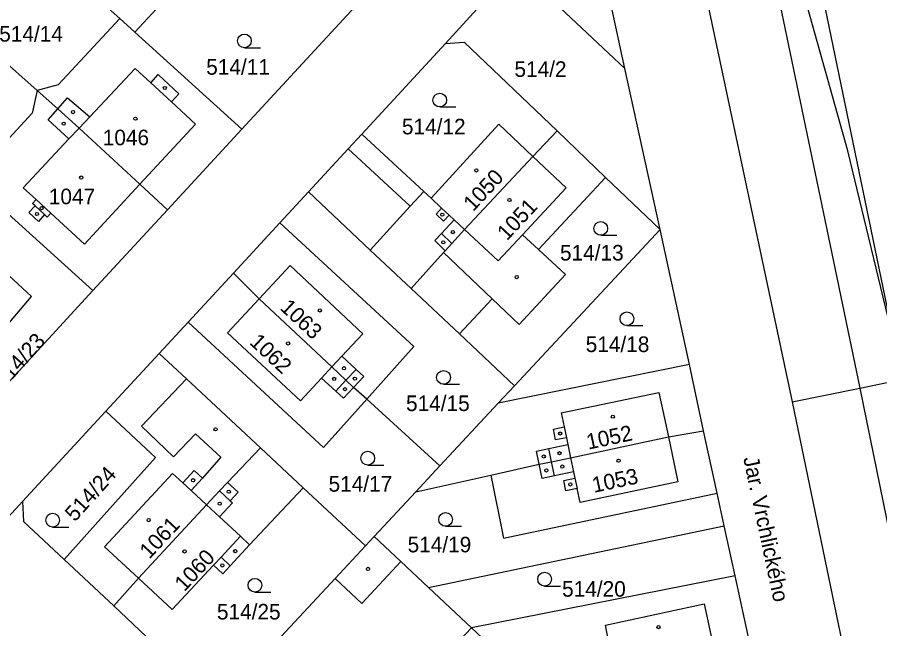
# Model space of a CAD drawing. Extents: x -679220 to -673243, y -1075091 to -1066557.
# Drawn here: x -675837.1 to -675742.9, y -1071866.6 to -1071799.9 of the extents above; entities that cross this region are included whole.
import ezdxf

# ---------------------------------------------------------------- set-up
doc = ezdxf.new("R2010")
doc.units = 0
for name, color, linetype in [('Hranice parcel', 7, 'Continuous'), ('Parcelní čísla', 7, 'Continuous'), ('Pop  PČ popisy', 7, 'Continuous'), ('Poz předměty', 7, 'Continuous'), ('Vnitřní kresba', 7, 'Continuous'), ('Značky budov', 7, 'Continuous'), ('Značky kultur', 7, 'Continuous')]:
    doc.layers.add(name, color=color, linetype=linetype)

msp = doc.modelspace()

# ---------------------------------------------------------------- linework, layer by layer
at = {"layer": 'Hranice parcel'}
for p, q in [((-675770.76, -1071805.49), (-675775, -1071786.1)), ((-675835.95, -1071790.96), (-675825.92, -1071800.04)), ((-675782.65, -1071794.34), (-675790.35, -1071802.75)), ((-675770.76, -1071805.49), (-675782.65, -1071794.34)), ((-675812.58, -1071812.11), (-675797.69, -1071795.96)), ((-675824.28, -1071801.52), (-675821.44, -1071798.48)), ((-675844.12, -1071799.72), (-675834.93, -1071807.9)), ((-675824.28, -1071801.52), (-675825.92, -1071800.04)), ((-675812.58, -1071812.11), (-675824.28, -1071801.52)), ((-675766.92, -1071823.05), (-675770.76, -1071805.49)), ((-675820.71, -1071820.92), (-675812.58, -1071812.11)), ((-675778.16, -1071812.31), (-675780.82, -1071815.1)), ((-675772.86, -1071817.38), (-675778.16, -1071812.31)), ((-675772.86, -1071817.38), (-675766.92, -1071823.05)), ((-675840.56, -1071819.13), (-675828.84, -1071829.74)), ((-675805.32, -1071818.96), (-675808.44, -1071822.34)), ((-675805.32, -1071818.96), (-675798.56, -1071825.31)), ((-675828.84, -1071829.74), (-675820.71, -1071820.92)), ((-675808.44, -1071822.34), (-675813.5, -1071827.82)), ((-675782.82, -1071840.12), (-675766.92, -1071823.05)), ((-675763.72, -1071837.81), (-675766.92, -1071823.05)), ((-675798.56, -1071825.31), (-675794.1, -1071829.51)), ((-675813.5, -1071827.82), (-675818.46, -1071833.19)), ((-675794.1, -1071829.51), (-675788.83, -1071834.47)), ((-675818.46, -1071833.19), (-675821.6, -1071836.59)), ((-675788.83, -1071834.47), (-675782.82, -1071840.12)), ((-675821.6, -1071836.59), (-675827.44, -1071842.91)), ((-675763.72, -1071837.81), (-675784.58, -1071842.01)), ((-675762.16, -1071845.04), (-675763.72, -1071837.81)), ((-675784.58, -1071842.01), (-675782.82, -1071840.12)), ((-675798.92, -1071841.57), (-675790.95, -1071848.86)), ((-675784.58, -1071842.01), (-675790.95, -1071848.86)), ((-675827.44, -1071842.91), (-675836.53, -1071852.75)), ((-675760.69, -1071851.83), (-675762.16, -1071845.04)), ((-675805.89, -1071851.26), (-675810.55, -1071846.9)), ((-675790.95, -1071848.86), (-675793.57, -1071851.68)), ((-675793.57, -1071851.68), (-675785.4, -1071849.86)), ((-675805.89, -1071851.26), (-675799.09, -1071857.6)), ((-675798.13, -1071856.58), (-675793.57, -1071851.68)), ((-675759.92, -1071855.39), (-675760.69, -1071851.83)), ((-675845.47, -1071862.48), (-675836.53, -1071852.75)), ((-675792.2, -1071862.14), (-675759.92, -1071855.39)), ((-675758.73, -1071860.87), (-675759.92, -1071855.39)), ((-675798.13, -1071856.58), (-675799.09, -1071857.6)), ((-675831.97, -1071859.1), (-675826.57, -1071864.15)), ((-675758.73, -1071860.87), (-675787.52, -1071866.53)), ((-675757.17, -1071868.06), (-675758.73, -1071860.87)), ((-675826.57, -1071864.15), (-675823.88, -1071861.12)), ((-675787.52, -1071866.53), (-675792.2, -1071862.14)), ((-675826.57, -1071864.15), (-675815.16, -1071874.86)), ((-675787.52, -1071866.53), (-675784.09, -1071869.74))]:
    msp.add_line(p, q, dxfattribs=at)
for points in [[(-675791.003, -1071658.205), (-675790.75, -1071659.46), (-675779.94, -1071713.34), (-675771.38, -1071755.76), (-675762.14, -1071796.42), (-675752.49, -1071841.88)], [(-675825.92, -1071800.04), (-675832.64, -1071807.29), (-675834.93, -1071807.9)], [(-675790.35, -1071802.75), (-675788.32, -1071802.61), (-675778.16, -1071812.31)], [(-675790.35, -1071802.75), (-675799.5, -1071812.66), (-675800.98, -1071814.26), (-675805.32, -1071818.96)], [(-675834.93, -1071807.9), (-675835.49, -1071810.37), (-675842.22, -1071817.63)], [(-675834.93, -1071807.9), (-675832.69, -1071809.89), (-675830.34, -1071811.99), (-675823.71, -1071818.12), (-675820.71, -1071820.92)], [(-675780.82, -1071815.1), (-675784.51, -1071811.58), (-675791.92, -1071819.66), (-675792.73, -1071818.92), (-675794.2, -1071820.51), (-675798.56, -1071825.31)], [(-675794.1, -1071829.51), (-675790.55, -1071825.58), (-675790.38, -1071825.4), (-675789.67, -1071824.61), (-675788.27, -1071823.06), (-675780.82, -1071815.1)], [(-675788.83, -1071834.47), (-675785.25, -1071830.63), (-675782.32, -1071833.43), (-675777.26, -1071827.98), (-675780.2, -1071825.24), (-675772.86, -1071817.38)], [(-675798.92, -1071841.57), (-675793.79, -1071835.84), (-675808.44, -1071822.34)], [(-675848.43, -1071843.7), (-675843.75, -1071838.95), (-675842.57, -1071838.65), (-675835.54, -1071830.36), (-675843.93, -1071822.65)], [(-675798.92, -1071841.57), (-675800.39, -1071840.3), (-675801.23, -1071839.51), (-675802.75, -1071838.07), (-675810.7, -1071830.63), (-675813.5, -1071827.82)], [(-675845.89, -1071846.03), (-675843.82, -1071845.98), (-675828.84, -1071829.74)], [(-675818.46, -1071833.19), (-675803.66, -1071846.86), (-675798.92, -1071841.57)], [(-675810.55, -1071846.9), (-675818.63, -1071839.36), (-675821.6, -1071836.59)], [(-675752.49, -1071841.88), (-675745.12, -1071840.38), (-675740.55, -1071839.44), (-675734.17, -1071838.14)], [(-675752.49, -1071841.88), (-675742.66, -1071889.28), (-675729.17, -1071951.83), (-675725.47, -1071968.71), (-675720.4, -1071992.09), (-675718.71, -1072000.24), (-675717.07, -1072008.06), (-675709.67, -1072042.49)], [(-675827.44, -1071842.91), (-675822.03, -1071847.94), (-675831.97, -1071859.1)], [(-675785.4, -1071849.86), (-675780.11, -1071848.69), (-675778.77, -1071848.41), (-675776.69, -1071847.97), (-675766.01, -1071845.71), (-675762.16, -1071845.04)], [(-675810.55, -1071846.9), (-675814.17, -1071850.66), (-675815.02, -1071851.58), (-675816.45, -1071853.12), (-675823.88, -1071861.12)], [(-675785.4, -1071849.86), (-675784.01, -1071856.75), (-675760.69, -1071851.83)], [(-675823.88, -1071861.12), (-675820.18, -1071864.55), (-675815.68, -1071859.71), (-675814.67, -1071860.64), (-675813.85, -1071859.76), (-675811.76, -1071857.47), (-675805.89, -1071851.26)], [(-675836.53, -1071852.75), (-675836.43, -1071854.92), (-675831.97, -1071859.1)], [(-675792.2, -1071862.14), (-675795.22, -1071859.31), (-675798.13, -1071856.58)], [(-675799.09, -1071857.6), (-675802.4, -1071861.16), (-675815.16, -1071874.86)], [(-675787.52, -1071866.53), (-675792.07, -1071871.33), (-675792.89, -1071872.21), (-675794.33, -1071873.74), (-675801.82, -1071881.71), (-675804.58, -1071884.78)]]:
    msp.add_lwpolyline(points, dxfattribs=at)
at = {"layer": 'Poz předměty'}
for p, q in [((-675750.23, -1071792.42), (-675741.3, -1071835.73)), ((-675754.78, -1071793.86), (-675748.18, -1071825.68)), ((-675746.4, -1071814.48), (-675752.28, -1071793.55)), ((-675741.3, -1071835.73), (-675746.4, -1071814.48)), ((-675748.18, -1071825.68), (-675745.12, -1071840.38)), ((-675745.12, -1071840.38), (-675738.42, -1071873.24))]:
    msp.add_line(p, q, dxfattribs=at)
at = {"layer": 'Vnitřní kresba'}
for p, q in [((-675829.19, -1071810.77), (-675824.22, -1071805.48)), ((-675824.22, -1071805.48), (-675822.53, -1071807.04)), ((-675822.53, -1071807.04), (-675821.72, -1071806.16)), ((-675821.72, -1071806.16), (-675819.47, -1071808.24)), ((-675820.28, -1071809.12), (-675822.53, -1071807.04)), ((-675819.47, -1071808.24), (-675820.28, -1071809.12)), ((-675832.69, -1071809.89), (-675831.63, -1071808.7)), ((-675831.63, -1071808.7), (-675829.19, -1071810.77)), ((-675820.28, -1071809.12), (-675817.64, -1071811.56)), ((-675833.75, -1071811.09), (-675832.69, -1071809.89)), ((-675831.46, -1071813.18), (-675833.75, -1071811.09)), ((-675830.34, -1071811.99), (-675829.19, -1071810.77)), ((-675831.46, -1071813.18), (-675830.34, -1071811.99)), ((-675823.71, -1071818.12), (-675817.64, -1071811.56)), ((-675799.5, -1071812.66), (-675792.73, -1071818.92)), ((-675836.46, -1071818.5), (-675831.46, -1071813.18)), ((-675800.98, -1071814.26), (-675794.2, -1071820.51)), ((-675780.82, -1071815.1), (-675777.18, -1071818.52)), ((-675835.05, -1071819.79), (-675836.46, -1071818.5)), ((-675829.77, -1071824.68), (-675823.71, -1071818.12)), ((-675781.94, -1071823.63), (-675777.18, -1071818.52)), ((-675835.83, -1071821.22), (-675835.15, -1071820.49)), ((-675835.45, -1071820.22), (-675835.05, -1071819.79)), ((-675835.15, -1071820.49), (-675835.45, -1071820.22)), ((-675834.12, -1071821.44), (-675835.15, -1071820.49)), ((-675835.05, -1071819.79), (-675833.44, -1071821.29)), ((-675791.92, -1071819.66), (-675790.77, -1071820.73)), ((-675834.8, -1071822.18), (-675835.83, -1071821.22)), ((-675834.12, -1071821.44), (-675834.8, -1071822.18)), ((-675833.83, -1071821.71), (-675834.12, -1071821.44)), ((-675833.44, -1071821.29), (-675833.83, -1071821.71)), ((-675829.77, -1071824.68), (-675833.44, -1071821.29)), ((-675791.38, -1071821.39), (-675790.77, -1071820.73)), ((-675790.57, -1071822.15), (-675791.38, -1071821.39)), ((-675790.77, -1071820.73), (-675789.96, -1071821.49)), ((-675789.96, -1071821.49), (-675790.57, -1071822.15)), ((-675789.96, -1071821.49), (-675789.41, -1071822)), ((-675789.41, -1071822), (-675790.8, -1071823.49)), ((-675789.41, -1071822), (-675788.27, -1071823.06)), ((-675788.27, -1071823.06), (-675784.59, -1071826.48)), ((-675790.8, -1071823.49), (-675791.51, -1071824.26)), ((-675791.51, -1071824.26), (-675790.38, -1071825.4)), ((-675790.8, -1071823.49), (-675789.67, -1071824.61)), ((-675784.59, -1071826.48), (-675781.94, -1071823.63)), ((-675781.94, -1071823.63), (-675780.2, -1071825.24)), ((-675785.25, -1071830.63), (-675790.55, -1071825.58)), ((-675810.7, -1071830.63), (-675807.31, -1071826.99)), ((-675799.38, -1071834.45), (-675807.31, -1071826.99)), ((-675814.16, -1071834.34), (-675810.7, -1071830.63)), ((-675814.16, -1071834.34), (-675806.19, -1071841.76)), ((-675801.66, -1071836.9), (-675799.38, -1071834.45)), ((-675802.75, -1071838.07), (-675801.66, -1071836.9)), ((-675801.66, -1071836.9), (-675800.12, -1071838.33)), ((-675803.88, -1071839.28), (-675802.75, -1071838.07)), ((-675800.12, -1071838.33), (-675801.23, -1071839.51)), ((-675800.12, -1071838.33), (-675799.28, -1071839.12)), ((-675818.63, -1071839.36), (-675823.56, -1071844.54)), ((-675806.19, -1071841.76), (-675803.88, -1071839.28)), ((-675802.34, -1071840.71), (-675803.88, -1071839.28)), ((-675799.28, -1071839.12), (-675800.39, -1071840.3)), ((-675801.23, -1071839.51), (-675802.34, -1071840.71)), ((-675800.39, -1071840.3), (-675801.5, -1071841.49)), ((-675801.5, -1071841.49), (-675802.34, -1071840.71)), ((-675777.72, -1071843.09), (-675767.04, -1071840.84)), ((-675767.04, -1071840.84), (-675766.01, -1071845.71)), ((-675777.72, -1071843.09), (-675777.4, -1071844.61)), ((-675823.56, -1071844.54), (-675820.05, -1071847.89)), ((-675778.57, -1071844.86), (-675777.4, -1071844.61)), ((-675778.33, -1071846.03), (-675778.57, -1071844.86)), ((-675777.4, -1071844.61), (-675777.15, -1071845.79)), ((-675820.05, -1071847.89), (-675817.64, -1071845.35)), ((-675817.64, -1071845.35), (-675814.89, -1071847.92)), ((-675777.15, -1071845.79), (-675778.33, -1071846.03)), ((-675777.15, -1071845.79), (-675777, -1071846.52)), ((-675766.01, -1071845.71), (-675764.98, -1071850.59)), ((-675779.08, -1071846.96), (-675777, -1071846.52)), ((-675777, -1071846.52), (-675776.69, -1071847.97)), ((-675780.42, -1071847.24), (-675779.08, -1071846.96)), ((-675780.11, -1071848.69), (-675780.42, -1071847.24)), ((-675778.77, -1071848.41), (-675779.08, -1071846.96)), ((-675814.89, -1071847.92), (-675816.88, -1071850.2)), ((-675779.79, -1071850.23), (-675780.11, -1071848.69)), ((-675778.45, -1071849.94), (-675778.77, -1071848.41)), ((-675776.69, -1071847.97), (-675776.37, -1071849.5)), ((-675827.58, -1071857.69), (-675820.15, -1071849.68)), ((-675820.15, -1071849.68), (-675819.04, -1071850.71)), ((-675819.04, -1071850.71), (-675817.78, -1071849.36)), ((-675817.78, -1071849.36), (-675816.88, -1071850.2)), ((-675776.37, -1071849.5), (-675778.45, -1071849.94)), ((-675776.37, -1071849.5), (-675776.22, -1071850.19)), ((-675816.88, -1071850.2), (-675818.13, -1071851.55)), ((-675814.17, -1071850.66), (-675813, -1071851.75)), ((-675778.45, -1071849.94), (-675779.79, -1071850.23)), ((-675777.44, -1071850.45), (-675776.22, -1071850.19)), ((-675777.2, -1071851.59), (-675777.44, -1071850.45)), ((-675776.22, -1071850.19), (-675775.98, -1071851.33)), ((-675764.98, -1071850.59), (-675775.66, -1071852.85)), ((-675819.04, -1071850.71), (-675818.13, -1071851.55)), ((-675818.13, -1071851.55), (-675816.45, -1071853.12)), ((-675813.85, -1071852.67), (-675815.02, -1071851.58)), ((-675775.98, -1071851.33), (-675777.2, -1071851.59)), ((-675775.66, -1071852.85), (-675775.98, -1071851.33)), ((-675813, -1071851.75), (-675813.85, -1071852.67)), ((-675816.45, -1071853.12), (-675815.02, -1071854.44)), ((-675815.02, -1071854.44), (-675813.59, -1071852.9)), ((-675813.85, -1071852.67), (-675813.59, -1071852.9)), ((-675815.02, -1071854.44), (-675812.75, -1071856.55)), ((-675814.85, -1071858.82), (-675812.75, -1071856.55)), ((-675812.75, -1071856.55), (-675811.76, -1071857.47)), ((-675823.88, -1071861.12), (-675827.58, -1071857.69)), ((-675815.68, -1071859.71), (-675814.85, -1071858.82)), ((-675814.85, -1071858.82), (-675813.85, -1071859.76)), ((-675795.22, -1071859.31), (-675799.47, -1071863.88)), ((-675799.47, -1071863.88), (-675802.4, -1071861.16)), ((-675772.89, -1071866.24), (-675762.11, -1071863.91)), ((-675762.11, -1071863.91), (-675761.04, -1071868.86)), ((-675772.57, -1071867.76), (-675772.89, -1071866.24))]:
    msp.add_line(p, q, dxfattribs=at)
at = {"layer": 'Značky budov'}
for centre in [(-675820.997, -1071807.619), (-675831.017, -1071810.249), (-675824.207, -1071810.969), (-675832.037, -1071811.509), (-675786.977, -1071816.619), (-675830.127, -1071817.399), (-675783.367, -1071819.849), (-675834.957, -1071821.379), (-675834.447, -1071820.739), (-675790.697, -1071821.449), (-675789.547, -1071823.349), (-675790.587, -1071824.469), (-675782.577, -1071828.259), (-675804.067, -1071831.899), (-675807.537, -1071835.499), (-675801.427, -1071838.209), (-675802.507, -1071839.369), (-675800.237, -1071839.339), (-675801.317, -1071840.489), (-675772.077, -1071843.499), (-675815.457, -1071844.879), (-675777.827, -1071845.329), (-675779.617, -1071847.839), (-675777.897, -1071847.479), (-675777.597, -1071848.939), (-675771.447, -1071848.299), (-675779.337, -1071849.359), (-675817.907, -1071850.429), (-675814.017, -1071851.679), (-675776.717, -1071850.889), (-675815.007, -1071852.989), (-675822.757, -1071854.779), (-675818.837, -1071858.199), (-675813.307, -1071858.169), (-675814.717, -1071859.729), (-675798.817, -1071860.109), (-675767.087, -1071866.459)]:
    msp.add_circle(centre, 0.175, dxfattribs=at)
at = {"layer": 'Značky kultur'}
for p, q in [((-675812.303, -1071803.23), (-675810.553, -1071803.23)), ((-675790.973, -1071809.69), (-675789.223, -1071809.69)), ((-675773.393, -1071823.69), (-675771.643, -1071823.69)), ((-675770.543, -1071833.55), (-675768.793, -1071833.55)), ((-675790.563, -1071839.95), (-675788.813, -1071839.95)), ((-675798.833, -1071848.77), (-675797.083, -1071848.77)), ((-675833.243, -1071855.54), (-675831.493, -1071855.54)), ((-675790.343, -1071855.45), (-675788.593, -1071855.45)), ((-675779.533, -1071861.98), (-675777.783, -1071861.98)), ((-675811.153, -1071862.64), (-675809.403, -1071862.64))]:
    msp.add_line(p, q, dxfattribs=at)
for centre in [(-675812.303, -1071802.48), (-675790.973, -1071808.94), (-675773.393, -1071822.94), (-675770.543, -1071832.8), (-675790.563, -1071839.2), (-675798.833, -1071848.02), (-675833.243, -1071854.79), (-675790.343, -1071854.7), (-675779.533, -1071861.23), (-675811.153, -1071861.89)]:
    msp.add_circle(centre, 0.75, dxfattribs=at)

# ---------------------------------------------------------------- texts
at = {"layer": 'Parcelní čísla'}
for s, p in [('514/14', (-675839.077, -1071802.56)), ('514/11', (-675816.477, -1071806.17)), ('514/2', (-675782.818, -1071806.41)), ('514/12', (-675795.107, -1071812.68)), ('1046', (-675827.774, -1071813.87)), ('1047', (-675833.664, -1071820.31)), ('514/13', (-675777.847, -1071826.45)), ('514/18', (-675775.037, -1071836.44)), ('514/15', (-675794.657, -1071842.88)), ('514/17', (-675803.117, -1071851.68)), ('514/19', (-675794.487, -1071858.3)), ('514/20', (-675777.617, -1071863.14)), ('514/25', (-675815.307, -1071865.63))]:
    msp.add_text(s, height=1.7, dxfattribs=at).set_placement(p)
for s, rotation, p in [('1050', 47, (-675787.326, -1071821.174)), ('1051', 47, (-675783.636, -1071824.364)), ('1063', 317, (-675808.514, -1071831.723)), ('514/23', 48, (-675838.579, -1071840.492)), ('1062', 317, (-675811.834, -1071835.493)), ('1052', 12, (-675774.762, -1071847.099)), ('514/24', 48, (-675830.809, -1071855.042)), ('1053', 12, (-675774.142, -1071851.809)), ('1061', 47, (-675822.676, -1071859.104)), ('1060', 47, (-675818.856, -1071862.664))]:
    msp.add_text(s, height=1.7, rotation=rotation, dxfattribs=at).set_placement(p)
at = {"layer": 'Pop  PČ popisy'}
msp.add_text('Jar. Vrchlického', height=1.7, rotation=282, dxfattribs=at).set_placement((-675757.848, -1071848.015))

doc.saveas('drawing.dxf')
